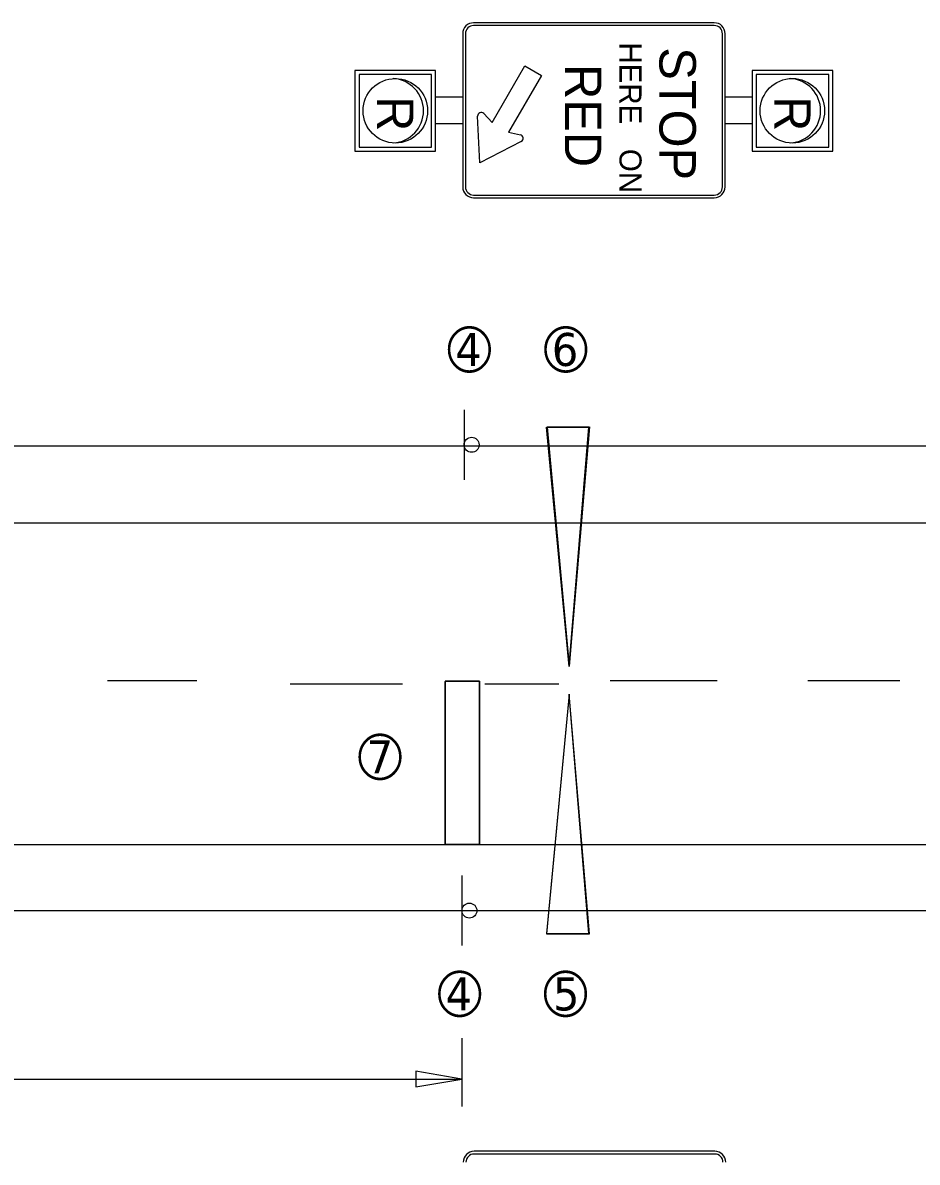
# Model space of a CAD drawing. Extents: x 10000 to 10825, y 10000 to 10530.
# Drawn here: x 10484.5 to 10560.5, y 10382.7 to 10479.5 of the extents above; entities that cross this region are included whole.
import ezdxf

# ---------------------------------------------------------------- set-up
doc = ezdxf.new("R2010")
doc.units = 0
for name, color, linetype in [('Default', 7, 'Continuous'), ('Dimension', 7, 'Continuous'), ('TextStructures', 7, 'Continuous')]:
    doc.layers.add(name, color=color, linetype=linetype)

msp = doc.modelspace()

# ---------------------------------------------------------------- linework, layer by layer
at = {"layer": 'Default'}
for p, q in [((10543.255, 10479.537), (10522.82, 10479.537)), ((10543.255, 10479.305), (10522.82, 10479.305)), ((10521.891, 10478.608), (10521.891, 10465.604)), ((10522.123, 10478.608), (10522.123, 10465.604)), ((10543.952, 10465.604), (10543.952, 10478.608)), ((10544.184, 10465.604), (10544.184, 10478.608)), ((10512.745, 10475.49), (10512.745, 10468.639)), ((10519.595, 10475.49), (10512.745, 10475.49)), ((10519.595, 10468.639), (10519.595, 10475.49)), ((10524.386, 10471.072), (10527.165, 10475.885)), ((10527.165, 10475.885), (10528.572, 10475.072)), ((10546.465, 10475.49), (10546.465, 10468.639)), ((10553.315, 10475.49), (10546.465, 10475.49)), ((10553.315, 10468.639), (10553.315, 10475.49)), ((10513.087, 10475.147), (10513.087, 10468.982)), ((10519.253, 10475.147), (10513.087, 10475.147)), ((10519.253, 10468.982), (10519.253, 10475.147)), ((10528.572, 10475.072), (10525.793, 10470.259)), ((10546.807, 10475.147), (10546.807, 10468.982)), ((10552.973, 10475.147), (10546.807, 10475.147)), ((10552.973, 10468.982), (10552.973, 10475.147)), ((10519.627, 10473.238), (10521.891, 10473.238)), ((10544.184, 10473.238), (10546.448, 10473.238)), ((10523.34, 10467.636), (10523.161, 10471.597)), ((10523.688, 10471.819), (10524.386, 10471.072)), ((10519.627, 10470.974), (10521.891, 10470.974)), ((10544.184, 10470.974), (10546.448, 10470.974)), ((10525.793, 10470.259), (10526.789, 10470.028)), ((10512.745, 10468.639), (10519.595, 10468.639)), ((10513.087, 10468.982), (10519.253, 10468.982)), ((10526.861, 10469.461), (10523.34, 10467.636)), ((10546.465, 10468.639), (10553.315, 10468.639)), ((10546.807, 10468.982), (10552.973, 10468.982)), ((10522.82, 10464.907), (10543.255, 10464.907)), ((10522.82, 10464.675), (10543.255, 10464.675)), ((10522.015, 10446.66), (10522.015, 10440.715)), ((10529.003, 10445.175), (10532.615, 10445.175)), ((10530.933, 10424.849), (10529.003, 10445.175)), ((10532.615, 10445.175), (10529.065, 10445.175)), ((10532.615, 10445.175), (10530.933, 10424.849)), ((10530.938, 10424.908), (10532.615, 10445.175)), ((10429.348, 10443.612), (10774.148, 10443.612)), ((10429.348, 10437.05), (10774.148, 10437.05)), ((10491.723, 10423.673), (10499.306, 10423.673)), ((10507.248, 10423.374), (10516.779, 10423.374)), ((10523.773, 10423.374), (10530.066, 10423.374)), ((10534.418, 10423.673), (10543.496, 10423.673)), ((10551.193, 10423.673), (10559.003, 10423.673)), ((10530.933, 10422.496), (10529.003, 10402.17)), ((10532.615, 10402.17), (10530.933, 10422.496)), ((10532.615, 10402.17), (10530.933, 10422.496)), ((10429.348, 10409.73), (10774.148, 10409.73)), ((10522.734, 10409.73), (10523.316, 10409.73)), ((10521.824, 10407.094), (10521.824, 10401.15)), ((10429.348, 10404.139), (10774.148, 10404.139)), ((10529.003, 10402.17), (10532.615, 10402.17)), ((10521.829, 10393.296), (10521.829, 10387.479)), ((10435.931, 10389.811), (10521.829, 10389.811)), ((10543.3, 10383.677), (10522.865, 10383.677)), ((10543.3, 10383.445), (10522.865, 10383.445))]:
    msp.add_line(p, q, dxfattribs=at)
for points in [[(10529.065, 10445.175), (10532.657, 10445.229), (10530.937, 10424.908)], [(10523.33, 10409.73), (10523.33, 10423.606), (10520.407, 10423.606), (10520.407, 10409.73)], [(10520.41, 10423.578), (10523.316, 10423.606), (10523.316, 10409.725), (10520.41, 10409.753)], [(10529.013, 10402.16), (10532.665, 10402.16), (10530.933, 10422.496)]]:
    msp.add_lwpolyline(points, close=True, dxfattribs=at)
for points in [[(10529.065, 10445.175), (10530.937, 10424.908)], [(10523.316, 10409.73), (10523.316, 10423.606), (10520.41, 10423.578), (10520.41, 10409.753)], [(10530.933, 10422.496), (10529.013, 10402.16)], [(10520.41, 10409.753), (10522.734, 10409.73)], [(10529.013, 10402.16), (10532.615, 10402.16)]]:
    msp.add_lwpolyline(points, dxfattribs=at)
for centre, radius in [((10516.17, 10472.064), 2.74), ((10549.89, 10472.065), 2.74), ((10522.652, 10443.687), 0.637), ((10522.461, 10404.122), 0.637)]:
    msp.add_circle(centre, radius, dxfattribs=at)
for centre, radius, start, end in [((10522.82, 10478.608), 0.929, 90, 180), ((10522.82, 10478.608), 0.697, 90, 180), ((10543.255, 10478.608), 0.929, 0, 90), ((10543.255, 10478.608), 0.697, 0, 90), ((10515.827, 10472.064), 2.74, 273.58332, 86.41668), ((10549.548, 10472.065), 2.74, 273.58332, 86.41668), ((10523.465, 10471.611), 0.305, 43.05632, 182.59674), ((10526.72, 10469.731), 0.305, 297.40328, 76.9437), ((10522.82, 10465.604), 0.929, 180, 270), ((10522.82, 10465.604), 0.697, 180, 270), ((10543.255, 10465.604), 0.929, 270, 360), ((10543.255, 10465.604), 0.697, 270, 360), ((10522.865, 10382.749), 0.929, 90, 180), ((10522.865, 10382.749), 0.697, 90, 180), ((10543.3, 10382.749), 0.929, 0, 90), ((10543.3, 10382.749), 0.697, 0, 90)]:
    msp.add_arc(centre, radius, start, end, dxfattribs=at)
at = {"layer": 'Dimension'}
msp.add_lwpolyline([(10521.829, 10389.811), (10517.924, 10390.472), (10517.924, 10389.149)], close=True, dxfattribs=at)

# ---------------------------------------------------------------- texts
at = {"layer": 'Default'}
for s, height, p in [('HERE   ON', 1.8726, (10535.209, 10477.871)), ('STOP', 3.0985, (10538.598, 10477.456)), ('RED', 3.0985, (10530.573, 10476.029))]:
    msp.add_text(s, height=height, rotation=270, dxfattribs=at).set_placement(p)
at = {"layer": 'TextStructures'}
for p in [(10514.627, 10473.3), (10548.348, 10473.299)]:
    msp.add_text('R', height=3.083, rotation=270, dxfattribs=at).set_placement(p)
for s, p in [('➃', (10520.609, 10450.04)), ('➅', (10528.798, 10450.04)), ('➆', (10513.021, 10415.434)), ('➃', (10519.786, 10395.303)), ('➄', (10528.772, 10395.303))]:
    msp.add_text(s, height=3.5, dxfattribs=at).set_placement(p)

doc.saveas('drawing.dxf')
